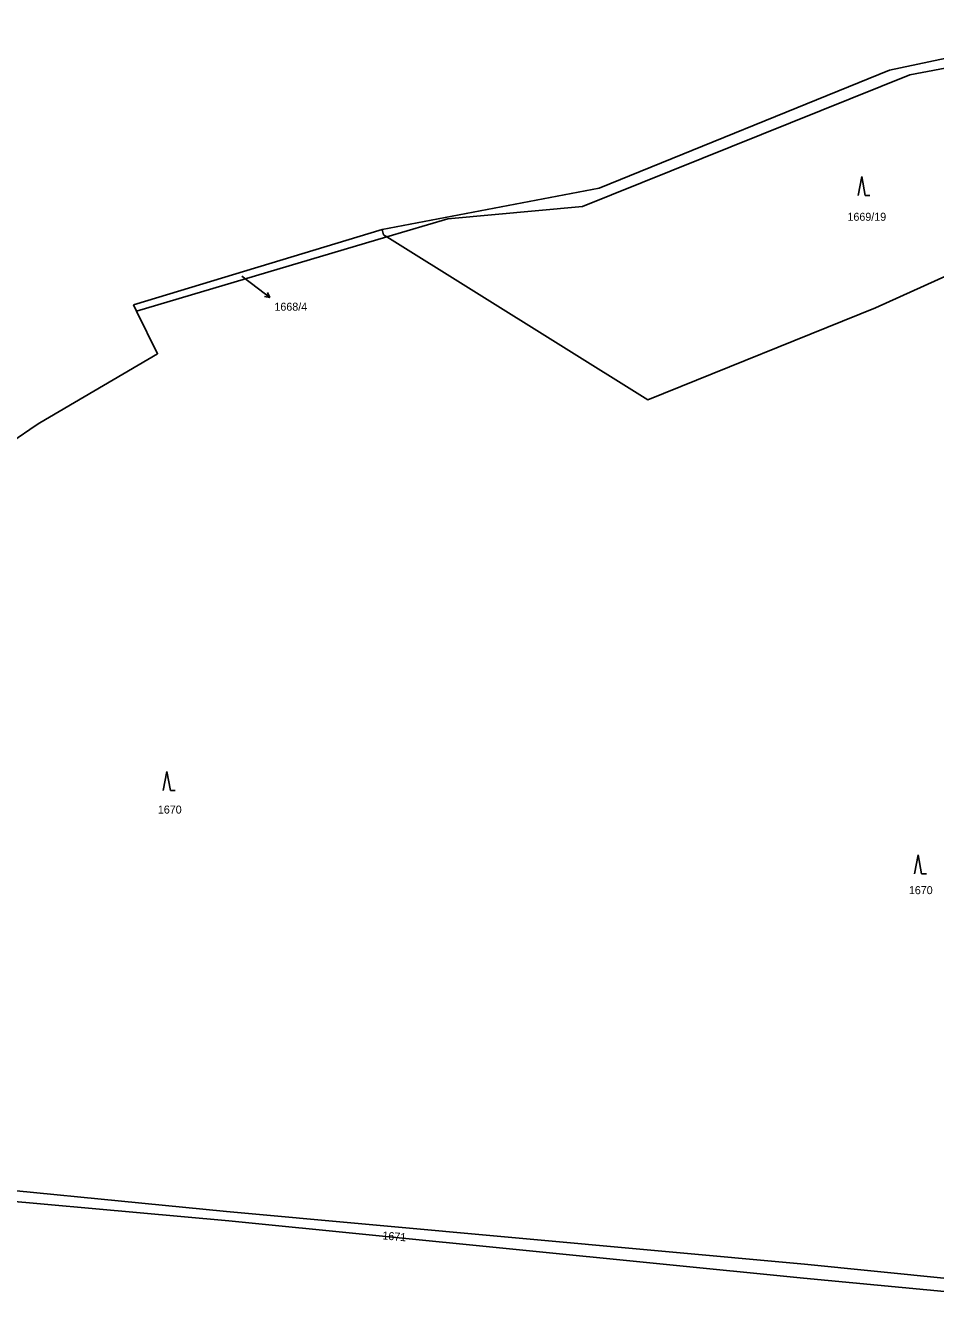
# Model space of a CAD drawing. Extents: x -724107 to -720612, y -1045267 to -1038441.
# Drawn here: x -723250.5 to -723057.3, y -1044252.9 to -1043979.4 of the extents above; entities that cross this region are included whole.
import ezdxf

# ---------------------------------------------------------------- set-up
doc = ezdxf.new("R2010")
doc.units = 0
for name, color, linetype in [('Hranice kat_území', 7, 'Continuous'), ('Hranice parcel', 7, 'Continuous'), ('Parcelní čísla', 7, 'Continuous'), ('Pop  PČ popisy', 7, 'Continuous'), ('Značky kultur', 7, 'Continuous')]:
    doc.layers.add(name, color=color, linetype=linetype)

msp = doc.modelspace()

# ---------------------------------------------------------------- linework, layer by layer
at = {"layer": 'Hranice kat_území'}
for p, q in [((-723174.77, -1044022.72), (-723227.6, -1044038.68)), ((-723227.6, -1044038.68), (-723226.91, -1044040.08))]:
    msp.add_line(p, q, dxfattribs=at)
for points in [[(-723022.51, -1043979.43), (-723066.98, -1043988.85), (-723128.64, -1044013.9), (-723174.77, -1044022.72)], [(-723226.91, -1044040.08), (-723222.46, -1044049.1), (-723247.47, -1044063.79)], [(-723247.47, -1044063.79), (-723248.28, -1044064.27), (-723253.45, -1044067.83)]]:
    msp.add_lwpolyline(points, dxfattribs=at)
at = {"layer": 'Hranice parcel'}
msp.add_line((-723226.91, -1044040.08), (-723173.74, -1044024.28), dxfattribs=at)
for points in [[(-723173.74, -1044024.28), (-723160.8, -1044020.44), (-723132.22, -1044017.79), (-723062.71, -1043989.85), (-723009.09, -1043979.75)], [(-723174.77, -1044022.72), (-723174.48, -1044023.82), (-723173.74, -1044024.28)], [(-723173.74, -1044024.28), (-723118.33, -1044058.87), (-723069.97, -1044039.36), (-723035.98, -1044024.01), (-723027.88, -1044022.59), (-723015.86, -1044024.2)], [(-723650.49, -1044652.19), (-723619.14, -1044596.15), (-723600.03, -1044570.94), (-723484.22, -1044419.22), (-723425, -1044341.84), (-723319.71, -1044259.97), (-723275.48, -1044224.61), (-723207.84, -1044231.25), (-723085.04, -1044242.45), (-722948.34, -1044256.18)], [(-723482.39, -1044420.61), (-723422.97, -1044343.38), (-723315.81, -1044259.07), (-723274.89, -1044227.15), (-723207.36, -1044233.26), (-723085.26, -1044245.44), (-722947.54, -1044258.44)]]:
    msp.add_lwpolyline(points, dxfattribs=at)
at = {"layer": 'Pop  PČ popisy'}
for p, q in [((-723204.55, -1044032.62), (-723201.03, -1044035.3)), ((-723201.03, -1044035.3), (-723198.63, -1044037.11)), ((-723198.63, -1044037.11), (-723199.73, -1044036.9)), ((-723198.63, -1044037.11), (-723199.13, -1044036.1))]:
    msp.add_line(p, q, dxfattribs=at)
at = {"layer": 'Značky kultur'}
for p, q in [((-723072.91, -1044011.48), (-723073.66, -1044015.48)), ((-723072.16, -1044015.48), (-723072.91, -1044011.48)), ((-723072.16, -1044015.48), (-723071.16, -1044015.48)), ((-723220.49, -1044137.82), (-723221.24, -1044141.82)), ((-723219.74, -1044141.82), (-723220.49, -1044137.82)), ((-723219.74, -1044141.82), (-723218.74, -1044141.82)), ((-723060.93, -1044155.51), (-723061.68, -1044159.51)), ((-723060.18, -1044159.51), (-723060.93, -1044155.51)), ((-723060.18, -1044159.51), (-723059.18, -1044159.51))]:
    msp.add_line(p, q, dxfattribs=at)

# ---------------------------------------------------------------- texts
at = {"layer": 'Parcelní čísla'}
for s, p in [('1669/19', (-723075.93, -1044020.85)), ('1668/4', (-723197.64, -1044039.95)), ('1670', (-723222.4, -1044146.75)), ('1670', (-723062.89, -1044163.86))]:
    msp.add_text(s, height=1.7, dxfattribs=at).set_placement(p)
msp.add_text('1671', height=1.7, rotation=355, dxfattribs=at).set_placement((-723174.77, -1044237.16))

doc.saveas('drawing.dxf')
